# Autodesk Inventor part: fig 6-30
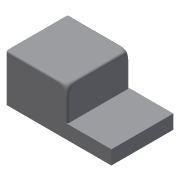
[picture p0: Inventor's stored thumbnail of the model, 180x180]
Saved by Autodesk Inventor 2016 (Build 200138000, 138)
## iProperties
Created: 2004-05
Part Number: fig 6-30
Document SubType Name: Modeling
Designer: CADCIM Technologies
Manufacturer: Standard
Standards Organization: Custom
Density: 1 g/cm^3
Material: Generic
Appearance: Default
Author: CADCIM Technologies
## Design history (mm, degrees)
node "Sketch1"
sketch "Sketch2"
  geometry: L1 (0.098, 47.711)-(0.098, 0.049); L2 (0.098, 0.049)-(-105.483, 0.049); L3 (-105.483, 0.049)-(-105.483, 14.192); L4 (-105.483, 14.192)-(-61.139, 14.192); L5 (-61.139, 14.192)-(-61.139, 47.711); L6 (-61.139, 47.711)-(0.098, 47.711)
  constraints: 12 end point, 3 parallel, 2 perpendicular, 1 vertical
extrude "Extrusion1" new body sketch "Sketch2" stored distance "d0" = 62.5; taper "d1" = 0 deg
fillet "Fillet6" dims "d43" = 10, "d44" = 10, "d45" = 10, "d46" = 10, "d47" = 10, "d48" = 10, "d49" = 2
body "Solid1"
